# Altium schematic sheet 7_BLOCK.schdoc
size 302 x 215 mm; Symbol: Sheet_A4; Device: Sheet_A4; @Project Name: Avaota A1 八核 AIoT 开发板; @Page No: 1; @Page Count: 13; @Update Date: 2024-02-28
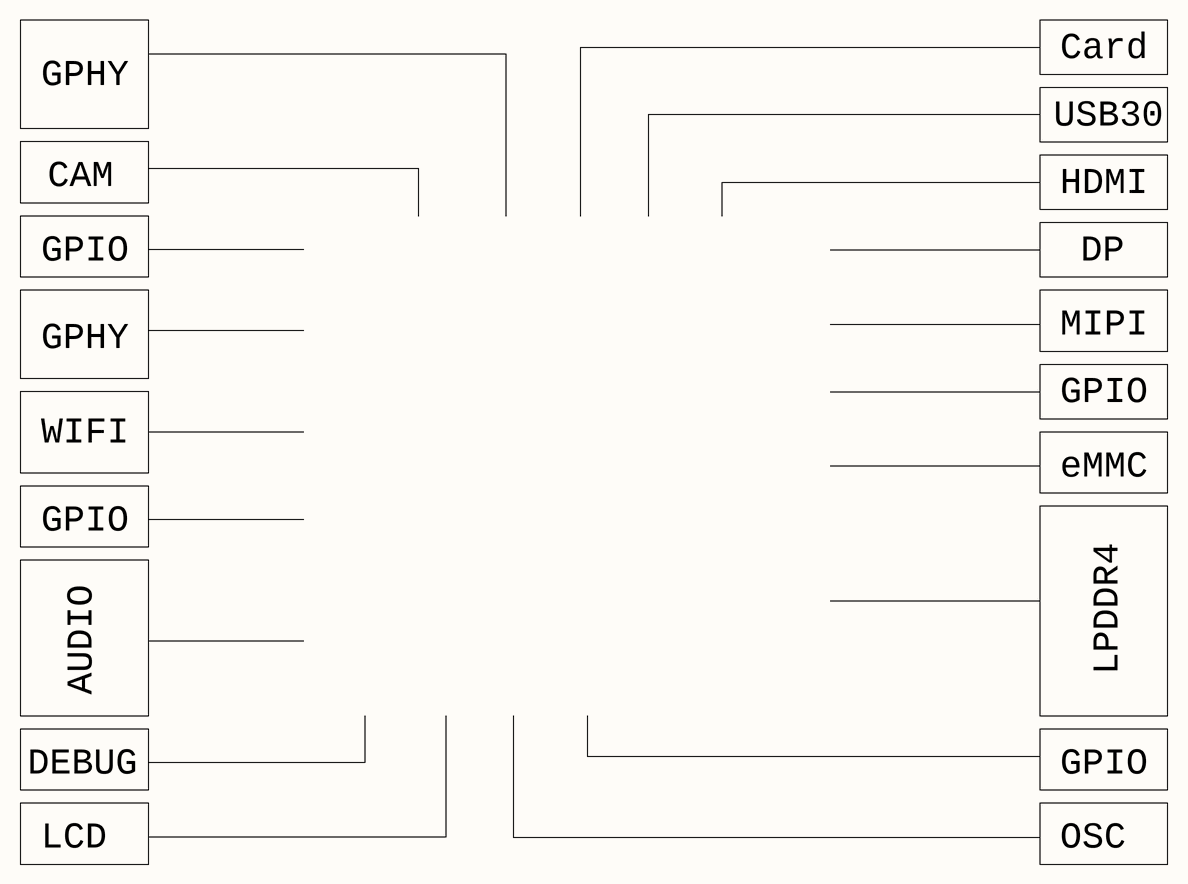
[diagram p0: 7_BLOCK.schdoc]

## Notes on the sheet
- GPHY
- USB30
- Card
- CAM
- GPIO
- HDMI
- DP
- MIPI
- WIFI
- eMMC
- LPDDR4
- AUDIO
- DEBUG
- LCD
- OSC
